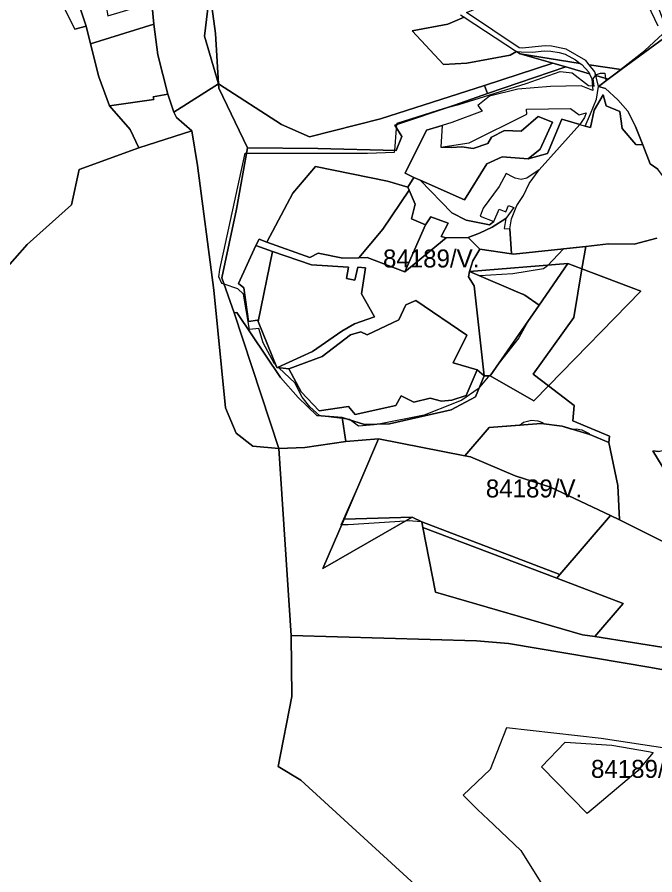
# Model space of a CAD drawing. Extents: x -477304 to -465429, y -1159113 to -1149210.
# Drawn here: x -476043 to -475512, y -1154135 to -1153420 of the extents above; entities that cross this region are included whole.
import ezdxf

# ---------------------------------------------------------------- set-up
doc = ezdxf.new("R2010")
doc.units = 0
for name, color, linetype in [('BPEJ_s', 7, 'Continuous'), ('PUPFL_s', 7, 'Continuous'), ('trav_porost_s', 7, 'Continuous'), ('zahrada_s', 7, 'Continuous')]:
    doc.layers.add(name, color=color, linetype=linetype)

msp = doc.modelspace()

# ---------------------------------------------------------------- linework, layer by layer
at = {"layer": 'BPEJ_s'}
for points in [[(-475509, -1153427), (-475517.5, -1153409)], [(-475509, -1153427), (-475517.5, -1153409)], [(-475790.7, -1153751.82), (-475799, -1153744.5), (-475805.5, -1153736.5), (-475811.5, -1153724.5), (-475824.88, -1153711.9), (-475825.99, -1153711.78), (-475826.72, -1153711.78), (-475827.76, -1153709.2), (-475828.5, -1153708.5), (-475838, -1153691), (-475841.5, -1153679), (-475849.5, -1153680), (-475854.5, -1153650.5), (-475859, -1153646), (-475870.46, -1153642.18), (-475872.5, -1153641.5), (-475875, -1153636), (-475874, -1153630), (-475853, -1153533), (-475851.96, -1153533), (-475751, -1153533), (-475728.5, -1153532), (-475728.39, -1153530.71), (-475726.86, -1153512.29), (-475726.59, -1153509.11), (-475726.5, -1153508), (-475687, -1153495.5), (-475683.62, -1153494.65), (-475675, -1153492.5), (-475619, -1153475), (-475590.5, -1153465), (-475580.5, -1153466), (-475567, -1153476.5), (-475563.7, -1153476.91), (-475562.34, -1153477.08), (-475562.99, -1153470.93), (-475561.09, -1153468.27), (-475560.98, -1153468.11), (-475560.95, -1153468.06), (-475560.44, -1153467.35), (-475556.88, -1153466.33), (-475553.31, -1153466.33), (-475552.77, -1153470.67), (-475552.67, -1153471.46), (-475552.54, -1153472.53), (-475550.84, -1153471.23), (-475540.39, -1153463.19), (-475520, -1153447.5), (-475505, -1153433.5)], [(-475824.88, -1153711.9), (-475825.99, -1153711.78), (-475826.72, -1153711.78), (-475827.76, -1153709.2), (-475828.5, -1153708.5), (-475838, -1153691), (-475841.5, -1153679), (-475849.5, -1153680), (-475854.5, -1153650.5), (-475859, -1153646), (-475870.46, -1153642.18), (-475872.5, -1153641.5), (-475875, -1153636), (-475874, -1153630), (-475853, -1153533), (-475851.96, -1153533), (-475751, -1153533), (-475728.5, -1153532), (-475728.39, -1153530.71), (-475726.86, -1153512.29), (-475726.59, -1153509.11), (-475726.5, -1153508), (-475687, -1153495.5), (-475683.62, -1153494.65), (-475675, -1153492.5), (-475619, -1153475), (-475590.5, -1153465), (-475580.5, -1153466), (-475567, -1153476.5), (-475563.7, -1153476.91), (-475562.34, -1153477.08), (-475562.99, -1153470.93), (-475561.09, -1153468.27), (-475560.98, -1153468.11), (-475560.95, -1153468.06), (-475560.44, -1153467.35), (-475556.88, -1153466.33), (-475553.31, -1153466.33), (-475552.77, -1153470.67), (-475552.67, -1153471.46), (-475552.54, -1153472.53), (-475550.84, -1153471.23), (-475540.39, -1153463.19), (-475520, -1153447.5), (-475505, -1153433.5)], [(-475510.04, -1153603.85), (-475528.97, -1153608.89), (-475550.34, -1153608.5), (-475569.29, -1153610.8), (-475587.68, -1153612.72), (-475601, -1153627), (-475604.5, -1153629.5), (-475630, -1153633.5), (-475657.46, -1153635.27), (-475625.43, -1153649.02), (-475621, -1153650.5), (-475619.57, -1153651.67), (-475608.06, -1153659.56), (-475617.27, -1153672.83), (-475625, -1153687), (-475643.27, -1153710.28), (-475649.02, -1153718.57), (-475649.77, -1153718.57), (-475650.5, -1153719.5), (-475657.63, -1153727.89), (-475659, -1153729.5), (-475672.5, -1153739), (-475678.5, -1153741.5), (-475704, -1153751.5), (-475741.66, -1153758.76), (-475745.5, -1153759.5), (-475758.5, -1153760.5), (-475765.25, -1153755.55), (-475766, -1153755), (-475767.8, -1153754.78), (-475768.33, -1153754.71), (-475772.1, -1153754.25), (-475790.5, -1153752), (-475790.7, -1153751.82), (-475799, -1153744.5), (-475805.5, -1153736.5), (-475811.5, -1153724.5), (-475824.88, -1153711.9)], [(-475510.04, -1153603.85), (-475528.97, -1153608.89), (-475550.34, -1153608.5), (-475569.29, -1153610.8), (-475587.68, -1153612.72), (-475601, -1153627), (-475604.5, -1153629.5), (-475630, -1153633.5), (-475657.46, -1153635.27), (-475625.43, -1153649.02), (-475621, -1153650.5), (-475619.57, -1153651.67), (-475608.06, -1153659.56), (-475617.27, -1153672.83), (-475625, -1153687), (-475643.27, -1153710.28), (-475649.02, -1153718.57), (-475649.77, -1153718.57), (-475650.5, -1153719.5), (-475657.63, -1153727.89), (-475659, -1153729.5), (-475672.5, -1153739), (-475678.5, -1153741.5), (-475704, -1153751.5), (-475741.66, -1153758.76), (-475745.5, -1153759.5), (-475758.5, -1153760.5), (-475765.25, -1153755.55), (-475766, -1153755), (-475767.8, -1153754.78), (-475768.33, -1153754.71), (-475772.1, -1153754.25), (-475790.5, -1153752), (-475790.7, -1153751.82)], [(-475624.25, -1153759.73), (-475621.1, -1153757.1), (-475614.5, -1153755.6), (-475609.2, -1153756), (-475605.3, -1153757.5), (-475604.03, -1153758.71), (-475588.9, -1153760.6), (-475581.23, -1153762.93), (-475577.3, -1153762.9), (-475572.6, -1153763.7), (-475566.5, -1153766.7), (-475566.24, -1153767.48), (-475565.95, -1153767.57), (-475550.09, -1153774.28), (-475542.44, -1153810.09), (-475541.07, -1153838.67), (-475548.73, -1153834.98), (-475590.76, -1153884.35), (-475705.28, -1153840.47), (-475705.74, -1153840.43), (-475713.39, -1153839.78), (-475716.16, -1153839.55), (-475719.84, -1153839.78), (-475767.28, -1153842.79), (-475772.65, -1153842.79), (-475773.11, -1153842.79), (-475756.99, -1153806.33), (-475741.9, -1153771.2), (-475670.03, -1153785.19), (-475649.72, -1153761.59), (-475624.25, -1153759.73)], [(-475586.5, -1154024), (-475547.5, -1154026.5), (-475517.05, -1154031.78), (-475513, -1154032.48), (-475526, -1154048), (-475561.51, -1154078.01), (-475568, -1154083.5), (-475606, -1154044.5), (-475586.5, -1154024)]]:
    msp.add_lwpolyline(points, dxfattribs=at)
for points in [[(-475588.9, -1153760.6), (-475581.23, -1153762.93), (-475577.3, -1153762.9), (-475572.6, -1153763.7), (-475566.5, -1153766.7), (-475566.24, -1153767.48), (-475565.95, -1153767.57), (-475550.09, -1153774.28), (-475542.44, -1153810.09), (-475541.07, -1153838.67), (-475548.73, -1153834.98), (-475590.76, -1153884.35), (-475705.28, -1153840.47), (-475705.74, -1153840.43), (-475713.39, -1153839.78), (-475716.16, -1153839.55), (-475719.84, -1153839.78), (-475767.28, -1153842.79), (-475772.65, -1153842.79), (-475773.11, -1153842.79), (-475756.99, -1153806.33), (-475741.9, -1153771.2), (-475670.03, -1153785.19), (-475649.72, -1153761.59), (-475624.25, -1153759.73), (-475621.1, -1153757.1), (-475614.5, -1153755.6), (-475609.2, -1153756), (-475605.3, -1153757.5), (-475604.03, -1153758.71)], [(-475561.51, -1154078.01), (-475568, -1154083.5), (-475606, -1154044.5), (-475586.5, -1154024), (-475547.5, -1154026.5), (-475517.05, -1154031.78), (-475513, -1154032.48), (-475526, -1154048)]]:
    msp.add_lwpolyline(points, close=True, dxfattribs=at)
at = {"layer": 'PUPFL_s'}
for points in [[(-476041.47, -1153331.29), (-475972.76, -1153341.58), (-475971.33, -1153395.47), (-475970.71, -1153408.74), (-475990.14, -1153412.95), (-475985.47, -1153427.23), (-475994.88, -1153429.59), (-476005.9, -1153407.45), (-476022.35, -1153373.44)], [(-475597.74, -1153443.76), (-475602.95, -1153443.6), (-475622.17, -1153445.5), (-475624.85, -1153445.17), (-475668.69, -1153415.63), (-475531.14, -1153360.32), (-475531.2, -1153370.12), (-475526.66, -1153384.3), (-475514.69, -1153395.34), (-475500.44, -1153434.27), (-475539.7, -1153463.29), (-475566.37, -1153459.27), (-475569.09, -1153455.81), (-475585.5, -1153446.34)], [(-475929, -1153425.46), (-475930.59, -1153410.82), (-475917.31, -1153404.6), (-475882.33, -1153398.08), (-475886.78, -1153435.3), (-475875.17, -1153475.08), (-475912.4, -1153498.87), (-475917.56, -1153483.75), (-475925.78, -1153451.1)], [(-475886.78, -1153435.3), (-475882.33, -1153398.08), (-475877.59, -1153433.1), (-475875.17, -1153475.08)], [(-475930.59, -1153410.82), (-475929, -1153425.46), (-475981.79, -1153441.83), (-475985.47, -1153427.23), (-475990.14, -1153412.95), (-475970.71, -1153408.74), (-475969.23, -1153408.42), (-475968.83, -1153410.81), (-475967.53, -1153418.45), (-475930.94, -1153407.6)], [(-475925.78, -1153451.1), (-475917.56, -1153483.75), (-475929.76, -1153485.99), (-475929.21, -1153488.3), (-475966.1, -1153493.56), (-475974.93, -1153469.29), (-475981.79, -1153441.83), (-475929, -1153425.46)], [(-475668.41, -1153458.08), (-475687.79, -1153459.15), (-475713.78, -1153431.01), (-475684.2, -1153425.47), (-475670.42, -1153419.59), (-475626.84, -1153448.33), (-475632.36, -1153451.19)], [(-475493.46, -1153459.75), (-475492.82, -1153484.93), (-475485.96, -1153525.23), (-475485.53, -1153549.13), (-475484.58, -1153602.24), (-475503.68, -1153602.19), (-475500.98, -1153601.49), (-475497.4, -1153591.91), (-475497, -1153568.53), (-475498.83, -1153560.34), (-475509.21, -1153546.37), (-475515.54, -1153541.79), (-475521.85, -1153525.95), (-475527.95, -1153510.61), (-475534.2, -1153498.06), (-475542.48, -1153488.38), (-475552.87, -1153479.13), (-475558.66, -1153477.28), (-475550.55, -1153471.31), (-475539.7, -1153463.29), (-475500.44, -1153434.27)], [(-475598.48, -1153448), (-475591.43, -1153449.06), (-475586.46, -1153450.46), (-475577.89, -1153455.17), (-475573.81, -1153458.15), (-475623.93, -1153450.13), (-475626.84, -1153448.33), (-475622.99, -1153448.58), (-475613.57, -1153448.64), (-475603.99, -1153447.8)], [(-475596.78, -1153457.97), (-475623.93, -1153450.13), (-475573.81, -1153458.15), (-475572.58, -1153459.04), (-475566.74, -1153465.34), (-475566.07, -1153466.83), (-475585.93, -1153461.1)], [(-475573.19, -1153476.72), (-475598.55, -1153477.36), (-475625.88, -1153479.58), (-475649.4, -1153485.57), (-475659.07, -1153493.19), (-475655.59, -1153498.07), (-475680.91, -1153507.43), (-475688.9, -1153509.91), (-475701.83, -1153513.93), (-475719.84, -1153549.68), (-475712.45, -1153553.33), (-475717.35, -1153561.4), (-475734.49, -1153556.24), (-475794.54, -1153544.05), (-475813.32, -1153566.21), (-475834.96, -1153607.13), (-475841.29, -1153604.8), (-475844.11, -1153609.9), (-475858.69, -1153641.76), (-475854.01, -1153645.2), (-475850.33, -1153673.17), (-475842.66, -1153672.16), (-475842.24, -1153673.19), (-475826.72, -1153711.78), (-475825.99, -1153711.78), (-475816.58, -1153712.84), (-475806.27, -1153731.98), (-475791.37, -1153747.72), (-475766.82, -1153744.11), (-475761.34, -1153750.78), (-475727.55, -1153743.35), (-475723.01, -1153735.4), (-475712.43, -1153740.61), (-475698.8, -1153737.11), (-475689.34, -1153739.63), (-475680.72, -1153739.01), (-475668.89, -1153734.97), (-475659.78, -1153713.64), (-475653.76, -1153718.54), (-475660.99, -1153736), (-475681.47, -1153746.89), (-475732.71, -1153758.52), (-475753.57, -1153759.08), (-475772.23, -1153753.44), (-475793.21, -1153751.6), (-475808.77, -1153736.65), (-475823.48, -1153720.08), (-475860.03, -1153665.68), (-475862.21, -1153666.07), (-475872.32, -1153636.78), (-475860.13, -1153579.58), (-475851.17, -1153528.5), (-475792.49, -1153528.95), (-475727.29, -1153530.74), (-475722.59, -1153519.2), (-475728.44, -1153509.73), (-475678.61, -1153492.97), (-475651.06, -1153483.16), (-475585.93, -1153461.1), (-475566.07, -1153466.83), (-475564.19, -1153471), (-475563.38, -1153480.81)], [(-475585.93, -1153461.1), (-475651.06, -1153483.16), (-475653.63, -1153476.63), (-475596.78, -1153457.97)], [(-475561.78, -1153465.12), (-475566.37, -1153459.27), (-475539.7, -1153463.29), (-475550.55, -1153471.31), (-475560.87, -1153468.33)], [(-475560.87, -1153468.33), (-475550.55, -1153471.31), (-475558.66, -1153477.28)], [(-475860.13, -1153579.58), (-475872.32, -1153636.78), (-475862.21, -1153666.07), (-475825.03, -1153779.08), (-475846.52, -1153777.32), (-475860.49, -1153766.45), (-475869.26, -1153745.4), (-475879, -1153647.09), (-475892.72, -1153543.15), (-475897.34, -1153514.33), (-475910.3, -1153503.15), (-475912.4, -1153498.87), (-475875.17, -1153475.08), (-475874.89, -1153478.85), (-475851.17, -1153528.5)], [(-475799.43, -1153519.25), (-475740.15, -1153504.46), (-475653.63, -1153476.63), (-475651.06, -1153483.16), (-475678.61, -1153492.97), (-475728.44, -1153509.73), (-475722.59, -1153519.2), (-475727.29, -1153530.74), (-475792.49, -1153528.95), (-475851.17, -1153528.5), (-475874.89, -1153478.85), (-475875.17, -1153475.08), (-475822.83, -1153509.17)], [(-475540.89, -1153498.35), (-475552.3, -1153493.56), (-475554.75, -1153484.27), (-475562.32, -1153497.18), (-475565.19, -1153511.69), (-475569.79, -1153510.4), (-475565.42, -1153500.31), (-475560.35, -1153488.09), (-475558.66, -1153477.28), (-475552.87, -1153479.13), (-475542.48, -1153488.38), (-475534.2, -1153498.06), (-475527.95, -1153510.61), (-475521.85, -1153525.95), (-475527.66, -1153525.75), (-475539.01, -1153512.42)], [(-475897.34, -1153514.33), (-475941.59, -1153528.51), (-475948.79, -1153513.24), (-475966.1, -1153493.56), (-475929.21, -1153488.3), (-475929.76, -1153485.99), (-475917.56, -1153483.75), (-475912.4, -1153498.87), (-475910.3, -1153503.15)], [(-475636.97, -1153514.1), (-475647.89, -1153519.53), (-475650.98, -1153524.94), (-475663.06, -1153529.12), (-475672.45, -1153527.72), (-475681.19, -1153528.16), (-475689.92, -1153527.88), (-475666.5, -1153524.3), (-475618.43, -1153500.42), (-475618.59, -1153496.19), (-475581.96, -1153495.66), (-475574.73, -1153501.1), (-475568.84, -1153499.25), (-475570.35, -1153503.17), (-475574.16, -1153508.94), (-475589.14, -1153504.68), (-475601.27, -1153533.38), (-475617.29, -1153537.75), (-475607.21, -1153529.51), (-475597.04, -1153507.15), (-475608.99, -1153502.36), (-475623.17, -1153514.55)], [(-475858.69, -1153641.76), (-475844.11, -1153609.9), (-475830.23, -1153614.94), (-475842.24, -1153673.19), (-475842.66, -1153672.16), (-475850.33, -1153673.17), (-475854.01, -1153645.2)], [(-475631.23, -1153616.85), (-475629.52, -1153617.08), (-475569.29, -1153610.8), (-475572.66, -1153629.41), (-475584.12, -1153624.95), (-475666.11, -1153631.56), (-475663.45, -1153622.65), (-475657.44, -1153613.04)], [(-475608.06, -1153659.56), (-475620.08, -1153651.32), (-475666.11, -1153631.56), (-475584.12, -1153624.95)], [(-475612.42, -1153739.33), (-475649.02, -1153718.57), (-475608.06, -1153659.56), (-475584.12, -1153624.95), (-475572.66, -1153629.41), (-475579.17, -1153669.95), (-475613.16, -1153717.34), (-475600.39, -1153727.01)], [(-475523.34, -1153648.1), (-475600.39, -1153727.01), (-475613.16, -1153717.34), (-475579.17, -1153669.95), (-475572.66, -1153629.41)], [(-475772.23, -1153753.44), (-475769.04, -1153773.27), (-475803.37, -1153778.4), (-475825.03, -1153779.08), (-475862.21, -1153666.07), (-475860.03, -1153665.68), (-475823.48, -1153720.08), (-475808.77, -1153736.65), (-475793.21, -1153751.6)], [(-475580.1, -1153756.17), (-475549.39, -1153768.9), (-475550.09, -1153774.28), (-475565.95, -1153767.57), (-475588.9, -1153760.6), (-475606.35, -1153758.42), (-475649.72, -1153761.59), (-475670.03, -1153785.19), (-475741.9, -1153771.2), (-475769.04, -1153773.27), (-475772.23, -1153753.44), (-475753.57, -1153759.08), (-475732.71, -1153758.52), (-475681.47, -1153746.89), (-475660.99, -1153736), (-475653.76, -1153718.54), (-475649.02, -1153718.57), (-475612.42, -1153739.33), (-475600.39, -1153727.01), (-475578.88, -1153743.31)], [(-475497.35, -1153838.39), (-475481.89, -1153835.14), (-475486.87, -1153824.6), (-475513.48, -1153781.22), (-475508.72, -1153781.62), (-475484.97, -1153775.68), (-475459.46, -1153829.31), (-475474.44, -1153866.8), (-475503.48, -1153852.62)], [(-475713.79, -1153836.29), (-475788.33, -1153879.31), (-475770.64, -1153838.12)], [(-475459.43, -1153885.41), (-475475.52, -1153910.09), (-475499, -1153946), (-475561.66, -1153935.99), (-475538.16, -1153908.48), (-475593.35, -1153887.4), (-475590.76, -1153884.35), (-475548.73, -1153834.98), (-475541.07, -1153838.67), (-475456.54, -1153880.98)], [(-475593.35, -1153887.4), (-475705.03, -1153845.03), (-475705.76, -1153840.29), (-475590.76, -1153884.35)], [(-475561.66, -1153935.99), (-475571.93, -1153934.58), (-475694.55, -1153898.89), (-475705.03, -1153845.03), (-475593.35, -1153887.4), (-475538.16, -1153908.48)]]:
    msp.add_lwpolyline(points, close=True, dxfattribs=at)
for points in [[(-475673.48, -1153417.57), (-475670.42, -1153419.59), (-475684.2, -1153425.47), (-475713.78, -1153431.01), (-475687.79, -1153459.15), (-475668.41, -1153458.08), (-475632.36, -1153451.19), (-475626.84, -1153448.33), (-475623.93, -1153450.13), (-475596.78, -1153457.97), (-475653.63, -1153476.63), (-475740.15, -1153504.46), (-475799.43, -1153519.25), (-475822.83, -1153509.17), (-475875.17, -1153475.08), (-475877.59, -1153433.1), (-475882.33, -1153398.08)], [(-476005.9, -1153407.45), (-475994.88, -1153429.59), (-475985.47, -1153427.23), (-475981.79, -1153441.83), (-475974.93, -1153469.29), (-475966.1, -1153493.56), (-475948.79, -1153513.24), (-475941.59, -1153528.51), (-475991.17, -1153546.59), (-475997.76, -1153576.14), (-476034.71, -1153609.09), (-476065.7, -1153644.11)], [(-476065.7, -1153644.11), (-476034.71, -1153609.09), (-475997.76, -1153576.14), (-475991.17, -1153546.59), (-475941.59, -1153528.51), (-475897.34, -1153514.33), (-475892.72, -1153543.15), (-475879, -1153647.09), (-475869.26, -1153745.4), (-475860.49, -1153766.45), (-475846.52, -1153777.32), (-475825.03, -1153779.08), (-475814.63, -1153935.2), (-475814.03, -1153985.87), (-475825.65, -1154044.41), (-475806.71, -1154055.75), (-475642.43, -1154206.13)], [(-475456.54, -1153880.98), (-475541.07, -1153838.67), (-475542.44, -1153810.09), (-475550.09, -1153774.28), (-475549.39, -1153768.9), (-475580.1, -1153756.17), (-475578.88, -1153743.31), (-475600.39, -1153727.01), (-475523.34, -1153648.1), (-475572.66, -1153629.41), (-475569.29, -1153610.8), (-475550.34, -1153608.5), (-475528.97, -1153608.89), (-475510.04, -1153603.85)], [(-475440.94, -1153975.29), (-475515.07, -1153961.8), (-475633.57, -1153941.86), (-475660.19, -1153939.52), (-475814.63, -1153935.2), (-475825.03, -1153779.08), (-475803.37, -1153778.4), (-475769.04, -1153773.27), (-475741.9, -1153771.2), (-475770.64, -1153838.12), (-475788.33, -1153879.31), (-475713.79, -1153836.29), (-475705.76, -1153840.29), (-475705.03, -1153845.03), (-475694.55, -1153898.89), (-475571.93, -1153934.58), (-475561.66, -1153935.99), (-475499, -1153946)], [(-475508.72, -1153781.62), (-475513.48, -1153781.22), (-475486.87, -1153824.6)], [(-475642.43, -1154206.13), (-475806.71, -1154055.75), (-475825.65, -1154044.41), (-475814.03, -1153985.87), (-475814.63, -1153935.2), (-475660.19, -1153939.52), (-475633.57, -1153941.86), (-475515.07, -1153961.8), (-475440.94, -1153975.29)], [(-475499.82, -1154029.51), (-475556.44, -1154021.02), (-475635.42, -1154012.08), (-475649.02, -1154046.75), (-475671.45, -1154068.19), (-475660.13, -1154079.7), (-475654.25, -1154085.13), (-475651.23, -1154087.99), (-475623.48, -1154114.25), (-475601.71, -1154149.02)]]:
    msp.add_lwpolyline(points, dxfattribs=at)
at = {"layer": 'trav_porost_s'}
msp.add_lwpolyline([(-475510.04, -1153603.85), (-475528.97, -1153608.89), (-475550.34, -1153608.5), (-475569.29, -1153610.8), (-475629.52, -1153617.08), (-475631.23, -1153616.85), (-475632.49, -1153596.14), (-475631.2, -1153587.68), (-475626.74, -1153576.47), (-475621.09, -1153568.23), (-475616.41, -1153558.15), (-475608.08, -1153546.94), (-475574.16, -1153508.94), (-475569.79, -1153510.4), (-475565.19, -1153511.69), (-475562.32, -1153497.18), (-475554.75, -1153484.27), (-475552.3, -1153493.56), (-475540.89, -1153498.35), (-475539.01, -1153512.42), (-475527.66, -1153525.75), (-475521.85, -1153525.95), (-475515.54, -1153541.79), (-475509.21, -1153546.37)], dxfattribs=at)
for points in [[(-475608.99, -1153502.36), (-475597.04, -1153507.15), (-475607.21, -1153529.51), (-475617.29, -1153537.75), (-475638.84, -1153536.12), (-475651.69, -1153541.78), (-475670.38, -1153571.99), (-475707.25, -1153555.51), (-475712.45, -1153553.33), (-475719.84, -1153549.68), (-475701.83, -1153513.93), (-475688.9, -1153509.91), (-475689.92, -1153527.88), (-475681.19, -1153528.16), (-475672.45, -1153527.72), (-475663.06, -1153529.12), (-475650.98, -1153524.94), (-475647.89, -1153519.53), (-475636.97, -1153514.1), (-475623.17, -1153514.55)], [(-475717.35, -1153561.4), (-475716.38, -1153563.69), (-475738.27, -1153596.43), (-475758.22, -1153620.22), (-475771.72, -1153620.37), (-475792.05, -1153616.34), (-475799.21, -1153620.04), (-475834.96, -1153607.13), (-475813.32, -1153566.21), (-475794.54, -1153544.05), (-475734.49, -1153556.24)], [(-475689.65, -1153602.53), (-475683.94, -1153591.38), (-475698.28, -1153585.94), (-475702.76, -1153592.78), (-475714.35, -1153587.68), (-475711.36, -1153575.52), (-475716.38, -1153563.69), (-475717.35, -1153561.4), (-475712.45, -1153553.33), (-475707.25, -1153555.51), (-475680.84, -1153582.64), (-475668.81, -1153588.94), (-475649.43, -1153592.59), (-475645.88, -1153589.88), (-475641.34, -1153579.73), (-475635.72, -1153581.96), (-475633.55, -1153576.51), (-475629.29, -1153578.27), (-475635.79, -1153587.57), (-475647.33, -1153594.57), (-475657.86, -1153599.67), (-475667.33, -1153603.37), (-475685.45, -1153603.49)], [(-475720.12, -1153631.87), (-475751.36, -1153619.88), (-475758.22, -1153620.22), (-475738.27, -1153596.43), (-475716.38, -1153563.69), (-475711.36, -1153575.52), (-475714.35, -1153587.68), (-475702.76, -1153592.78)], [(-475720.12, -1153631.87), (-475702.76, -1153592.78), (-475698.28, -1153585.94), (-475683.94, -1153591.38), (-475689.65, -1153602.53), (-475685.45, -1153603.49)], [(-475637.19, -1153595.7), (-475632.49, -1153596.14), (-475631.23, -1153616.85), (-475657.44, -1153613.04), (-475667.33, -1153603.37), (-475657.86, -1153599.67), (-475647.33, -1153594.57), (-475635.79, -1153587.57)], [(-475771.72, -1153620.37), (-475758.22, -1153620.22), (-475751.36, -1153619.88), (-475720.12, -1153631.87), (-475685.45, -1153603.49), (-475667.33, -1153603.37), (-475657.44, -1153613.04), (-475663.45, -1153622.65), (-475666.11, -1153631.56), (-475666.94, -1153636.16), (-475662.16, -1153643.5), (-475653.76, -1153718.54), (-475659.78, -1153713.64), (-475679.65, -1153707.76), (-475668.37, -1153684.59), (-475710.78, -1153655.91), (-475719.18, -1153659.33), (-475724.9, -1153671.81), (-475751.48, -1153684.4), (-475756.76, -1153681.89), (-475765.33, -1153684.36), (-475788.93, -1153702.48), (-475816.58, -1153712.84), (-475825.99, -1153711.78), (-475796.97, -1153698.24), (-475772.53, -1153681.24), (-475761.93, -1153675.38), (-475745.21, -1153669.42), (-475756.1, -1153650.12), (-475752.63, -1153628.5), (-475759.01, -1153627.94), (-475761.59, -1153638.97), (-475768.59, -1153637.57), (-475766.96, -1153628.11), (-475797.79, -1153626.06), (-475830.23, -1153614.94), (-475844.11, -1153609.9), (-475841.29, -1153604.8), (-475834.96, -1153607.13), (-475799.21, -1153620.04), (-475792.05, -1153616.34)], [(-475830.23, -1153614.94), (-475797.79, -1153626.06), (-475766.96, -1153628.11), (-475768.59, -1153637.57), (-475761.59, -1153638.97), (-475759.01, -1153627.94), (-475752.63, -1153628.5), (-475756.1, -1153650.12), (-475745.21, -1153669.42), (-475761.93, -1153675.38), (-475772.53, -1153681.24), (-475796.97, -1153698.24), (-475825.99, -1153711.78), (-475826.72, -1153711.78), (-475842.24, -1153673.19)], [(-475666.11, -1153631.56), (-475620.08, -1153651.32), (-475608.06, -1153659.56), (-475649.02, -1153718.57), (-475653.76, -1153718.54), (-475662.16, -1153643.5), (-475666.94, -1153636.16)], [(-475765.33, -1153684.36), (-475756.76, -1153681.89), (-475751.48, -1153684.4), (-475724.9, -1153671.81), (-475719.18, -1153659.33), (-475710.78, -1153655.91), (-475668.37, -1153684.59), (-475679.65, -1153707.76), (-475659.78, -1153713.64), (-475668.89, -1153734.97), (-475680.72, -1153739.01), (-475689.34, -1153739.63), (-475698.8, -1153737.11), (-475712.43, -1153740.61), (-475723.01, -1153735.4), (-475727.55, -1153743.35), (-475761.34, -1153750.78), (-475766.82, -1153744.11), (-475791.37, -1153747.72), (-475806.27, -1153731.98), (-475816.58, -1153712.84), (-475788.93, -1153702.48)], [(-475550.09, -1153774.28), (-475542.44, -1153810.09), (-475541.07, -1153838.67), (-475548.73, -1153834.98), (-475598.68, -1153811.42), (-475628.03, -1153801.86), (-475665.26, -1153786.1), (-475670.03, -1153785.19), (-475649.72, -1153761.59), (-475606.35, -1153758.42), (-475588.9, -1153760.6), (-475565.95, -1153767.57)], [(-475713.79, -1153836.29), (-475770.64, -1153838.12), (-475741.9, -1153771.2), (-475670.03, -1153785.19), (-475665.26, -1153786.1), (-475628.03, -1153801.86), (-475598.68, -1153811.42), (-475548.73, -1153834.98), (-475590.76, -1153884.35), (-475705.76, -1153840.29)]]:
    msp.add_lwpolyline(points, close=True, dxfattribs=at)
at = {"layer": 'zahrada_s'}
msp.add_lwpolyline([(-475638.84, -1153536.12), (-475617.29, -1153537.75), (-475601.27, -1153533.38), (-475589.14, -1153504.68), (-475574.16, -1153508.94), (-475608.08, -1153546.94), (-475618.43, -1153553.69), (-475623.13, -1153554.87), (-475628.05, -1153553.86), (-475629.63, -1153553), (-475635.51, -1153549.81), (-475641.43, -1153560.73), (-475654.62, -1153578.92), (-475657.19, -1153585.39), (-475645.88, -1153589.88), (-475649.43, -1153592.59), (-475668.81, -1153588.94), (-475680.84, -1153582.64), (-475707.25, -1153555.51), (-475670.38, -1153571.99), (-475651.69, -1153541.78)], close=True, dxfattribs=at)

# ---------------------------------------------------------------- texts
at = {"layer": 'BPEJ_s'}
for p in [(-475738.19, -1153628.26), (-475652.49, -1153819.98), (-475564.9, -1154053.75)]:
    msp.add_text('84189/V.', height=15, dxfattribs=at).set_placement(p)

doc.saveas('drawing.dxf')
